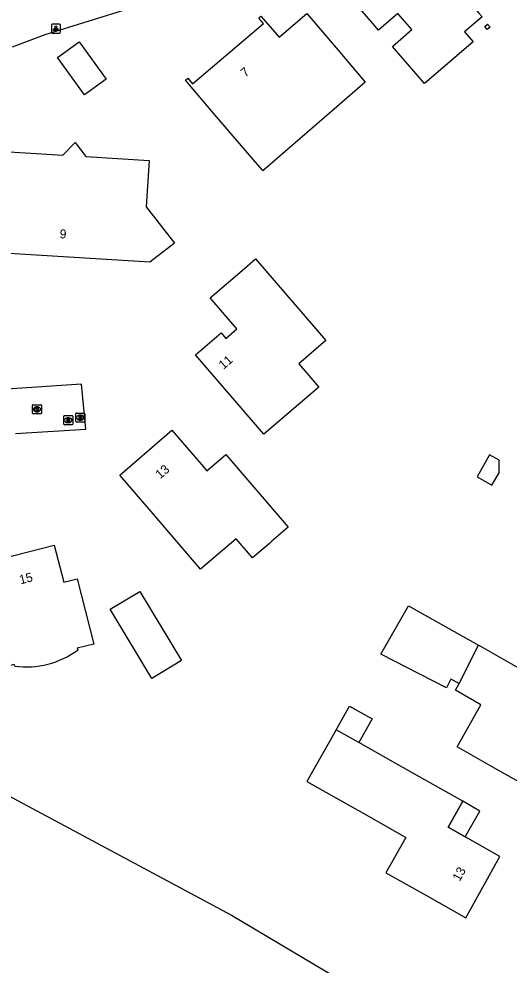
# Model space of a CAD drawing. Extents: x 163268 to 164360, y 381529 to 382285.
# Drawn here: x 163510.8 to 163565, y 381582.7 to 381687.6 of the extents above; entities that cross this region are included whole.
import ezdxf

# ---------------------------------------------------------------- set-up
doc = ezdxf.new("R2010")
doc.units = 0
for name, color, linetype in [('IMGEO_Brandkraan', 7, 'Continuous'), ('IMGEO_Hek', 7, 'Continuous'), ('IMGEO_Kolk', 7, 'Continuous'), ('IMGEO_Lichtpunt', 7, 'Continuous'), ('IMGEO_Loofbos', 7, 'Continuous'), ('IMGEO_Pand', 7, 'Continuous'), ('IMGEO_Pand_nummerreeks', 7, 'Continuous'), ('IMGEO_Pand_overbouw', 7, 'Continuous'), ('IMGEO_Rijbaan_lokaal_open', 7, 'Continuous'), ('IMGEO_Rioolput', 7, 'Continuous')]:
    doc.layers.add(name, color=color, linetype=linetype)

msp = doc.modelspace()

# ---------------------------------------------------------------- linework, layer by layer
at = {"layer": 'IMGEO_Brandkraan'}
for p, q in [((163517.05, 381642.96), (163517.05, 381643.81)), ((163517.12, 381643.89), (163517.97, 381643.89)), ((163517.56, 381643.11), (163517.53, 381643.11)), ((163517.54, 381643.67), (163517.56, 381643.67)), ((163518.05, 381643.81), (163518.05, 381642.96)), ((163517.97, 381642.89), (163517.12, 381642.89))]:
    msp.add_line(p, q, dxfattribs=at)
for points in [[(163517.05, 381642.96), (163517.05, 381643.81)], [(163517.12, 381643.89), (163517.97, 381643.89)], [(163517.39, 381643.59), (163517.39, 381643.19), (163517.61, 381643.19)], [(163517.63, 381643.59), (163517.39, 381643.59)], [(163517.57, 381643.51), (163517.52, 381643.51), (163517.52, 381643.43)], [(163517.52, 381643.43), (163517.57, 381643.43)], [(163517.58, 381643.35), (163517.52, 381643.35), (163517.52, 381643.27)], [(163517.52, 381643.27), (163517.58, 381643.27)], [(163518.05, 381643.81), (163518.05, 381642.96)], [(163517.97, 381642.89), (163517.12, 381642.89)]]:
    msp.add_lwpolyline(points, dxfattribs=at)
for centre, radius, start, end in [((163517.12, 381643.81), 0.0765, 91.552, 178.448), ((163517.12, 381643.81), 0.0765, 91.552, 178.448), ((163517.12, 381642.96), 0.0765, 181.552, 268.448), ((163517.12, 381642.96), 0.0765, 181.552, 268.448), ((163517.57, 381643.47), 0.0379, 267.8285, 90.9355), ((163517.58, 381643.31), 0.0404, 269.8759, 90.5077), ((163517.61, 381643.44), 0.251, 268.6676, 293.5347), ((163517.63, 381643.44), 0.145, 59.4692, 91.5367), ((163517.66, 381643.49), 0.0922, 285.5137, 58.1501), ((163517.66, 381643.3), 0.105, 301.3115, 78.989), ((163517.97, 381643.81), 0.0765, 1.552, 88.448), ((163517.97, 381643.81), 0.0765, 1.552, 88.448), ((163517.97, 381642.96), 0.0765, 271.552, 358.448), ((163517.97, 381642.96), 0.0765, 271.552, 358.448)]:
    msp.add_arc(centre, radius, start, end, dxfattribs=at)
for centre, major_axis, ratio, start_param, end_param in [((163517.53, 381643.39), (-0.387, 0.002), 0.722429, 4.712389, 7.853982), ((163517.56, 381643.39), (-0.39, 0.002), 0.717154, 1.570796, 4.712389)]:
    msp.add_ellipse(centre, major_axis=major_axis, ratio=ratio, start_param=start_param, end_param=end_param, dxfattribs=at)
at = {"layer": 'IMGEO_Hek'}
msp.add_lwpolyline([(163534.27, 381588.25), (163555.58, 381575.61)], dxfattribs=at)
at = {"layer": 'IMGEO_Kolk'}
for p, q in [((163512.25, 381643.88), (163512.25, 381644.74)), ((163512.32, 381644.81), (163513.18, 381644.81)), ((163512.76, 381644.03), (163512.73, 381644.03)), ((163512.74, 381644.59), (163512.76, 381644.59)), ((163513.25, 381644.74), (163513.25, 381643.88)), ((163513.18, 381643.81), (163512.32, 381643.81))]:
    msp.add_line(p, q, dxfattribs=at)
for points in [[(163512.25, 381643.88), (163512.25, 381644.74)], [(163512.32, 381644.81), (163513.18, 381644.81)], [(163512.57, 381644.51), (163512.69, 381644.51), (163512.69, 381644.36), (163512.82, 381644.51), (163512.99, 381644.51), (163512.84, 381644.36), (163512.99, 381644.11), (163512.84, 381644.11), (163512.76, 381644.28), (163512.69, 381644.21), (163512.69, 381644.11), (163512.57, 381644.11), (163512.57, 381644.51)], [(163513.25, 381644.74), (163513.25, 381643.88)], [(163513.18, 381643.81), (163512.32, 381643.81)]]:
    msp.add_lwpolyline(points, dxfattribs=at)
for centre, start, end in [((163512.32, 381644.74), 91.552, 178.448), ((163512.32, 381644.74), 91.552, 178.448), ((163513.17, 381644.74), 1.552, 88.448), ((163513.17, 381644.74), 1.552, 88.448), ((163512.32, 381643.89), 181.552, 268.448), ((163512.32, 381643.89), 181.552, 268.448), ((163513.17, 381643.89), 271.552, 358.448), ((163513.17, 381643.89), 271.552, 358.448)]:
    msp.add_arc(centre, 0.0765, start, end, dxfattribs=at)
for centre, major_axis, ratio, start_param, end_param in [((163512.74, 381644.31), (-0.387, 0.002), 0.722429, 4.712389, 7.853982), ((163512.76, 381644.31), (-0.39, 0.002), 0.717154, 1.570796, 4.712389)]:
    msp.add_ellipse(centre, major_axis=major_axis, ratio=ratio, start_param=start_param, end_param=end_param, dxfattribs=at)
at = {"layer": 'IMGEO_Lichtpunt'}
for p, q in [((163515.25, 381686.98), (163514.44, 381686.98)), ((163515.25, 381686.98), (163514.44, 381686.98)), ((163514.35, 381686.89), (163514.35, 381686.08)), ((163514.35, 381686.89), (163514.35, 381686.08)), ((163514.44, 381685.98), (163515.25, 381685.98)), ((163514.44, 381685.98), (163515.25, 381685.98)), ((163515.34, 381686.08), (163515.34, 381686.89)), ((163515.34, 381686.08), (163515.34, 381686.89))]:
    msp.add_line(p, q, dxfattribs=at)
for points in [[(163514.72, 381686.55), (163514.76, 381686.52), (163514.57, 381686.26), (163514.53, 381686.29), (163514.72, 381686.55)], [(163514.82, 381686.5), (163514.87, 381686.5), (163514.87, 381686.18), (163514.82, 381686.18), (163514.82, 381686.5)], [(163514.93, 381686.52), (163514.97, 381686.55), (163515.16, 381686.29), (163515.12, 381686.26), (163514.93, 381686.52)]]:
    msp.add_lwpolyline(points, dxfattribs=at)
msp.add_circle((163514.85, 381686.68), 0.0994, dxfattribs=at)
for centre, start, end in [((163514.44, 381686.89), 90, 180), ((163514.44, 381686.89), 90, 180), ((163515.25, 381686.89), 0, 90), ((163515.25, 381686.89), 0, 90), ((163514.44, 381686.08), 180, 270), ((163514.44, 381686.08), 180, 270), ((163515.25, 381686.08), 270, 0), ((163515.25, 381686.08), 270, 360)]:
    msp.add_arc(centre, 0.0946, start, end, dxfattribs=at)
at = {"layer": 'IMGEO_Loofbos'}
msp.add_lwpolyline([(163442.6, 381660.01), (163441.97, 381658.51), (163446.05, 381651.32), (163447.99, 381636.71), (163448.36, 381617.31), (163459.91, 381615.93), (163467.61, 381615.15), (163500.11, 381607.37), (163500.96, 381607.17), (163500.85, 381606.17), (163534.27, 381588.25), (163555.58, 381575.61)], dxfattribs=at)
at = {"layer": 'IMGEO_Pand'}
for points in [[(163561.71, 381688.16), (163562.02, 381687.8), (163560.07, 381686.12), (163561.02, 381685.02), (163555.64, 381680.4), (163552.11, 381684.52), (163554.26, 381686.37), (163552.71, 381688.17), (163550.56, 381686.32), (163550.15, 381686.79), (163546.9, 381690.59), (163552.68, 381695.55), (163553.58, 381694.51), (163557.16, 381697.59), (163556.27, 381698.63), (163557.68, 381699.84), (163560.94, 381696.04), (163562.77, 381693.91), (163559.31, 381690.94), (163561.71, 381688.16)], [(163549.08, 381680.55), (163545.93, 381677.82), (163537.75, 381670.73), (163537.7, 381670.79), (163536.71, 381671.95), (163535.4, 381673.48), (163532.43, 381676.95), (163529.19, 381680.76), (163529.46, 381680.99), (163529.98, 381680.37), (163537.82, 381687.05), (163537.3, 381687.65), (163537.55, 381687.87), (163539.55, 381685.53), (163542.63, 381688.15), (163545.87, 381684.35), (163549.08, 381680.55)], [(163562.6, 381686.38), (163562.32, 381686.7), (163562.64, 381686.98), (163562.92, 381686.66), (163562.6, 381686.38)], [(163518.03, 381679.15), (163515.03, 381683.27), (163517.43, 381685.02), (163520.43, 381680.9), (163518.03, 381679.15)], [(163525.26, 381660.61), (163504.85, 381661.87), (163502.51, 381664.88), (163506.38, 381667.89), (163506.7, 381673.03), (163515.63, 381672.48), (163516.99, 381673.85), (163518.18, 381672.32), (163525.16, 381671.89), (163524.85, 381666.75), (163527.97, 381662.72), (163525.26, 381660.61)], [(163543.96, 381646.77), (163541.67, 381644.8), (163537.88, 381641.54), (163530.31, 381650.34), (163533.14, 381652.78), (163533.66, 381652.17), (163534.88, 381653.21), (163531.92, 381656.66), (163535.71, 381659.92), (163536.93, 381660.97), (163544.71, 381651.92), (163541.74, 381649.36), (163543.96, 381646.77)], [(163540.57, 381631.25), (163538.76, 381629.69), (163538.48, 381629.45), (163536.61, 381627.84), (163534.79, 381629.97), (163530.87, 381626.6), (163525.18, 381633.23), (163521.92, 381637.02), (163527.7, 381641.99), (163530.96, 381638.2), (163531.56, 381637.49), (163533.65, 381639.29), (163540.57, 381631.25)], [(163561.47, 381636.81), (163563.12, 381635.89), (163563.9, 381637.27), (163563.92, 381638.67), (163562.85, 381639.27), (163561.47, 381636.81)], [(163510.29, 381615.85), (163510.24, 381616.05), (163508.4, 381615.58), (163506.55, 381622.8), (163508.03, 381623.18), (163506.98, 381627.29), (163514.67, 381629.26)], [(163514.67, 381629.26), (163515.73, 381625.15), (163517.21, 381625.53), (163519.06, 381618.3), (163517.22, 381617.83), (163517.27, 381617.64)], [(163525.47, 381614.5), (163520.86, 381622.18), (163524.14, 381624.14), (163528.74, 381616.47), (163525.47, 381614.5)], [(163559.47, 381613.95), (163558.57, 381614.41), (163558.08, 381613.45), (163550.81, 381617.19), (163553.88, 381622.55), (163561.64, 381618.16)], [(163561.64, 381618.16), (163561.83, 381618.06), (163565.19, 381616.15), (163567.63, 381614.78), (163566.02, 381611.94), (163567.94, 381610.86), (163571.77, 381608.69), (163568, 381601.96), (163563.65, 381604.42), (163559.26, 381606.91), (163561.9, 381611.58), (163559.07, 381613.18), (163559.47, 381613.95)], [(163559.47, 381613.95), (163561.64, 381618.16)], [(163545.87, 381608.8), (163547.35, 381611.43), (163549.86, 381610.02), (163548.37, 381607.39)], [(163545.87, 381608.8), (163542.63, 381603.09), (163549.51, 381599.2), (163553.6, 381596.88), (163551.38, 381592.97), (163555.87, 381590.43), (163560.23, 381587.97), (163563.99, 381594.77), (163560.16, 381596.93), (163558.26, 381598.01), (163559.89, 381600.88), (163557.44, 381602.26), (163552.74, 381604.92), (163548.37, 381607.39)], [(163548.37, 381607.39), (163545.87, 381608.8)]]:
    msp.add_lwpolyline(points, dxfattribs=at)
msp.add_arc((163511.57, 381625.38), 9.61, 262.3619, 306.355, dxfattribs=at)
at = {"layer": 'IMGEO_Pand_overbouw'}
msp.add_lwpolyline([(163561.79, 381599.8), (163559.89, 381600.88), (163558.26, 381598.01), (163560.16, 381596.93)], close=True, dxfattribs=at)
at = {"layer": 'IMGEO_Rijbaan_lokaal_open'}
for points in [[(163510.05, 381684.46), (163513.65, 381685.84), (163523.18, 381688.77), (163532.97, 381691.97), (163539.45, 381694.52), (163545.29, 381697.41), (163552.77, 381702.06), (163557.23, 381705.6), (163562.77, 381711.15)], [(163510.39, 381641.64), (163518.17, 381642.09), (163517.69, 381647.08), (163509.42, 381646.55)]]:
    msp.add_lwpolyline(points, dxfattribs=at)
at = {"layer": 'IMGEO_Rioolput'}
for p, q in [((163515.71, 381642.68), (163515.71, 381643.53)), ((163515.78, 381643.61), (163516.64, 381643.61)), ((163516.2, 381643.38), (163516.22, 381643.38)), ((163516.71, 381643.53), (163516.71, 381642.68)), ((163516.64, 381642.6), (163515.78, 381642.6)), ((163516.22, 381642.83), (163516.2, 381642.83))]:
    msp.add_line(p, q, dxfattribs=at)
for points in [[(163515.71, 381642.68), (163515.71, 381643.53)], [(163515.78, 381643.61), (163516.64, 381643.61)], [(163516.3, 381643.3), (163516.05, 381643.3), (163516.05, 381642.9)], [(163516.05, 381642.9), (163516.17, 381642.9), (163516.17, 381643.07), (163516.18, 381643.07)], [(163516.23, 381643.22), (163516.17, 381643.22), (163516.17, 381643.14)], [(163516.17, 381643.14), (163516.22, 381643.14)], [(163516.23, 381643.04), (163516.3, 381642.9), (163516.44, 381642.9), (163516.37, 381643.03)], [(163516.71, 381643.53), (163516.71, 381642.68)], [(163516.64, 381642.6), (163515.78, 381642.6)]]:
    msp.add_lwpolyline(points, dxfattribs=at)
for centre, radius, start, end in [((163515.79, 381643.53), 0.0765, 91.552, 178.448), ((163515.79, 381643.53), 0.0765, 91.552, 178.448), ((163516.18, 381643.01), 0.0533, 26.0293, 88.6989), ((163516.21, 381643.33), 0.19, 274.7715, 282.9687), ((163516.23, 381643.13), 0.0964, 77.0061, 93.1865), ((163516.25, 381643.18), 0.0378, 276.6634, 79.6772), ((163516.3, 381643.19), 0.109, 350.3612, 89.416), ((163516.3, 381643.19), 0.112, 277.5842, 350.9817), ((163516.28, 381642.98), 0.108, 29.5134, 73.7905), ((163516.63, 381643.53), 0.0765, 1.552, 88.448), ((163516.63, 381643.53), 0.0765, 1.552, 88.448), ((163515.79, 381642.68), 0.0765, 181.552, 268.448), ((163515.79, 381642.68), 0.0765, 181.552, 268.448), ((163516.63, 381642.68), 0.0765, 271.552, 358.448), ((163516.63, 381642.68), 0.0765, 271.552, 358.448)]:
    msp.add_arc(centre, radius, start, end, dxfattribs=at)
for centre, major_axis, ratio, start_param, end_param in [((163516.2, 381643.1), (-0.387, 0.002), 0.722429, 4.712389, 7.853982), ((163516.22, 381643.1), (-0.39, 0.002), 0.717154, 1.570796, 4.712389)]:
    msp.add_ellipse(centre, major_axis=major_axis, ratio=ratio, start_param=start_param, end_param=end_param, dxfattribs=at)

# ---------------------------------------------------------------- texts
at = {"layer": 'IMGEO_Pand_nummerreeks'}
for s, rotation, p in [('7', 40.4623, (163535.82, 381681.04)), ('9', 356.3388, (163515.24, 381663.26)), ('11', 40.7011, (163533.39, 381648.67)), ('13', 40.6857, (163526.39, 381636.54)), ('15', 14.3626, (163510.93, 381624.91)), ('13', 60.9971, (163559.55, 381591.94))]:
    msp.add_text(s, height=1, rotation=rotation, dxfattribs=at).set_placement(p)

doc.saveas('drawing.dxf')
